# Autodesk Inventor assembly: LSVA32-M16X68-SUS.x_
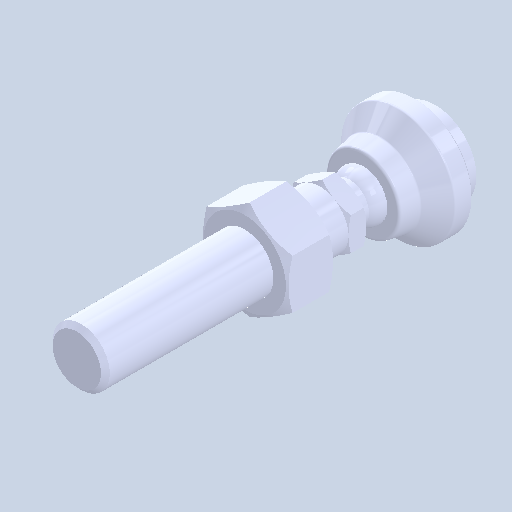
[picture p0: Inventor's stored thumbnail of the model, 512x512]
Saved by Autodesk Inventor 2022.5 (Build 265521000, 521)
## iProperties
Created: 2024-08
Part Number: LSVA32-M16X68-SUS.x_
Document SubType Name: Assembly
Designer: ImaoCorp
Author: ImaoCorp
Sending System: SOLIDWORKS 2022-2022290
MC: AMD64
MC_MODEL: Intel64 Family 6 Model 60 Stepping 3, GenuineIntel
OS: Windows_NT
FRU: Parasolid Version 33.1, build 260,  4-25-2022
FORMAT: text
GUISE: transmit
KEY: FILELSVA32-M16X68-SUS.x_t
DATE: Fri Aug 23 16:07:01 2024
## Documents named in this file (4)
- X:\14_SW2022-Inv2022\06_2024-10新製品(SME)\ELS_データ\l\lsva32-m16x68-sus\LSVA32-M16X68-SUS.x_.iam
- X:\14_SW2022-Inv2022\06_2024-10新製品(SME)\ELS_データ\l\lsva32-m16x68-sus\LSVA32-M16X68-SUS_01.ipt
- X:\14_SW2022-Inv2022\06_2024-10新製品(SME)\ELS_データ\l\lsva32-m16x68-sus\LSVA32-M16X68-SUS_02.ipt
- X:\14_SW2022-Inv2022\06_2024-10新製品(SME)\ELS_データ\l\lsva32-m16x68-sus\LSVA32-M16X68-SUS_03.ipt
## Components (3 placed, 3 different names)
1. LSVA32-M16X68-SUS_01
2. LSVA32-M16X68-SUS_02
3. LSVA32-M16X68-SUS_03
